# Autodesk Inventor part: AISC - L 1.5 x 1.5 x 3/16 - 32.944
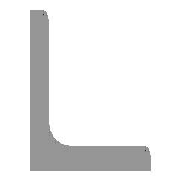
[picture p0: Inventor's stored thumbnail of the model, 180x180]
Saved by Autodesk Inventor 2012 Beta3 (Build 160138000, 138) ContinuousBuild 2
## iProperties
Created: 2010-11
Part Number: AISC - L 1.5 x 1.5 x 3/16 - 32.944
Material: Steel, Mild
Description: Angle Steel
Document SubType Name: Modeling
Standard: ANSI
Designer: Beta-8540w
Standards Organization: ANSI
Language: en-US
Size Designation: L 1.5 x 1.5 x 3/16
Categories: <MemberInstance><Categories><Category DisplayName="Structural Shapes" InternalName="089c4875-fa83-4c05-b084-43b9cc11f5ed" Mnemonic="GRDR"><CategoryParameter Dis
Stock Number: L 1.5 x 1.5 x 3/16
Density: 7.86 g/cm^3
IsCustomPart: 1
_CCFamilyMember: 5
_CCFamilyDisplayName: ANSI L (Equal angles) - Angle Steel
_FrameMemberDoc: Frame Member File
_Version: 15.0.0
_GetPNFromCC: 1
G_L: 32.944 in
G_W: 1.500 in
G_H: 1.500 in
Author: Beta-8540w
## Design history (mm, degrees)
node "Start plane"
node "End plane"
sketch "Sketch"
  geometry: L1 (38.1, 0)-(0, 0); L2 (0, 0)-(0, 38.1); L3 (0, 38.1)-(2.476, 38.1); L4 (4.762, 35.814)-(4.762, 9.589); L5 (9.588, 4.763)-(35.814, 4.763); L6 (38.1, 2.477)-(38.1, 0); L7 (0, -11.041)-(0, 31.538); L8 (-11.041, 0)-(31.538, 0); L9 (0, 48.496)-(0, -20.964) reference; L10 (-20.964, 0)-(48.496, 0) reference; A1 r 4.826 centre (9.588, 9.589) between (4.762, 9.589) and (9.588, 4.763); A2 r 2.286 centre (2.476, 35.814) between (4.762, 35.814) and (2.476, 38.1); A3 r 2.286 centre (35.814, 2.477) between (38.1, 2.477) and (35.814, 4.763); 3 further points
  constraints: 16 end point, 6 point on circle, 6 point on line, 6 tangent, 4 parallel, 3 centre point, 2 collinear, 1 equal radius, 1 horizontal, 1 perpendicular
  dimensions: "d0" = 38.1 distance between parallel lines of L6 L2 (= G_H); "d1" = 38.1 distance between parallel lines of L3 L1 (= G_H); "d2" = 4.7625 distance between parallel lines of L2 L4 (= G_T); "d3" = 4.7625 distance between parallel lines of L1 L5 (= G_T); "d10" = 0 distance between parallel lines of L7 L2 (computed from ex); "d11" = 0 distance between parallel lines of L8 L1 (computed from d10); "d14" = 4.826 radius of A1 (= G_IR); "d15" = 2.286 radius of A2 (= G_ER)
extrude "Body" new body sketch "Sketch" stored distance "d4" = 836.76542 (= G_L); taper "d5" = 0 deg
node "Driven Length"
  sketch "Sketch3"
    geometry: L1 (0, 0)-(10, 0) reference
    constraints: 2 end point, 1 horizontal
  workplane "Work Plane3"
  sketch "Sketch4"
    geometry: L1 (-2, 0)-(12, 0) reference; L2 (-2, 836.765)-(12, 836.765) reference
    dimensions: "d17" = 836.76542 distance between parallel lines of L1 L2 (derived)
body "Solid1"
other parameters: "G_H" = 38.1 [user parameter; used in 2 equation terms], "G_T" = 4.7625 [user parameter; used in 2 equation terms], "G_ER" = 2.286 [user parameter; used in 1 equation term], "G_IR" = 4.826 [user parameter; used in 1 equation term], "G_L" = 836.76542 (= d17) [user parameter; used in 1 equation term], "ex" = 0 [user parameter; used in 1 equation term], "G_OFFSET_START" = 0 [user parameter; used in 1 equation term], "G_OFFSET_END" = 0 [user parameter; used in 1 equation term], "d12" = 0 (computed from G_OFFSET_START), "d13" = 836.76542 (= G_OFFSET_END + B_L), "B_L" = 836.76542 [user parameter; used in 1 equation term], "d16" = 90 deg, "MAS" = 0.26787 [user parameter]
